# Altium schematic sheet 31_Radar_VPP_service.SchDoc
size 289 x 396 mm
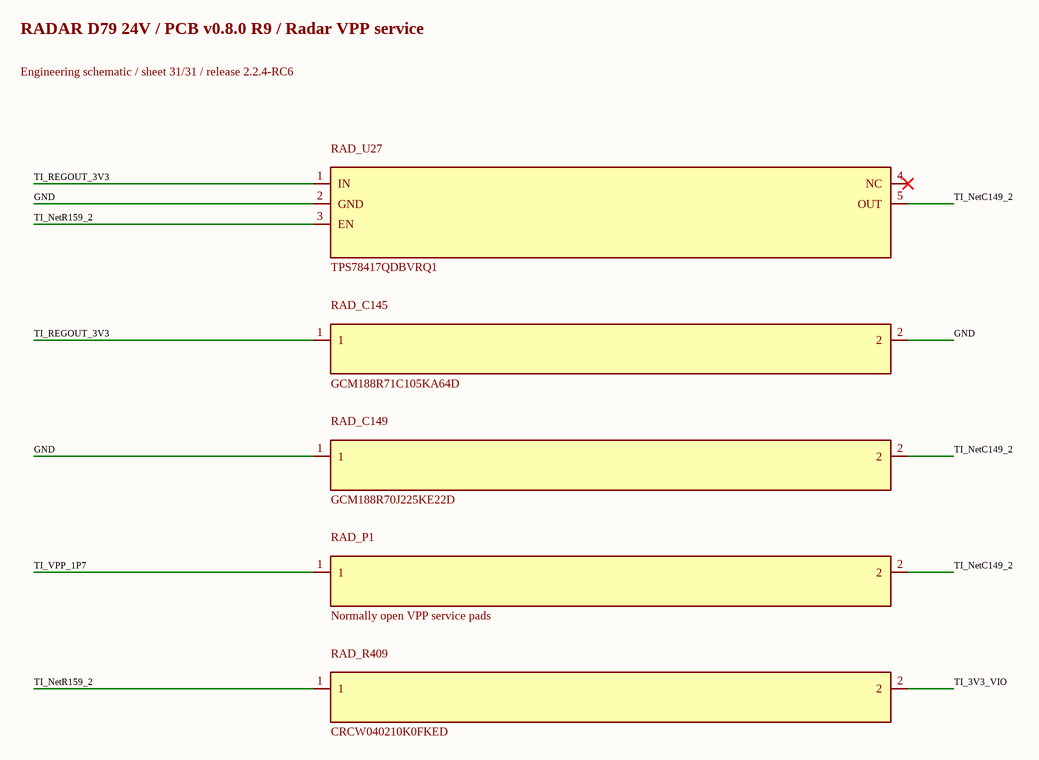
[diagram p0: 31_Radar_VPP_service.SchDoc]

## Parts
RAD_C145  GCM188R71C105KA64D  [0603L]
RAD_C149  GCM188R70J225KE22D  [0603L]
RAD_P1  Normally open VPP service pads  [VPP_SERVICE_SMT_D1p5_P2p5]
RAD_R409  CRCW040210K0FKED  [0402L]
RAD_U27  TPS78417QDBVRQ1  [DBV0005A-MFG]

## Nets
GND: RAD_C145.2 RAD_C149.1 RAD_U27.2(GND)
TI_3V3_VIO: RAD_R409.2
TI_NetC149_2: RAD_C149.2 RAD_P1.2 RAD_U27.5(OUT)
TI_NetR159_2: RAD_R409.1 RAD_U27.3(EN)
TI_REGOUT_3V3: RAD_C145.1 RAD_U27.1(IN)
TI_VPP_1P7: RAD_P1.1

Not connected (* = marked no-connect by the designer): RAD_U27 4(NC)*

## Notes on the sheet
- RADAR D79 24V / PCB v0.8.0 R9 / Radar VPP service
- Engineering schematic / sheet 31/31 / release 2.2.4-RC6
